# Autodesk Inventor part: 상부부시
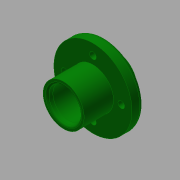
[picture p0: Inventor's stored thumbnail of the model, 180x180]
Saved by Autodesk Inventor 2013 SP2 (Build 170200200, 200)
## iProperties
Created: 2015-12
Part Number: 상부부시
Material: 강철, 연강
Document SubType Name: Modeling
Designer: mduedu
Density: 7.86 g/cm^3
Author: mduedu
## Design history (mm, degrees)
sketch "스케치1"
  geometry: C1 r 10.5 at (0, 0); C2 r 8 at (0, 0); 1 further point
  constraints: 2 centre point, 2 coincident
  dimensions: "d1" = 21 diameter of C1; "d3" = 16 diameter of C2
extrude "돌출1" new body sketch "스케치1" distance "d4" = 12; taper "d6" = 0 deg; dims "d5" = 15, "d7" = 0
sketch "스케치2"
  geometry: C1 r 20 at (0, 0); C2 r 10.5 at (0, 0) reference; 1 further point
  constraints: 1 centre point, 1 coincident
  dimensions: "d8" = 40 diameter of C1
extrude "돌출2" join sketch "스케치2" distance "d10" = 6; taper "d11" = 0 deg
chamfer "모따기1" distance "d12" = 2.5; stored, may be unused: second distance "d13" = 2, angle "d14" = 10 deg
chamfer "모따기2" distance "d15" = 2.5; stored, may be unused: second distance "d16" = 2, angle "d17" = 10 deg
fillet "모깎기1" dims "d18" = 1
fillet "모깎기2" dims "d19" = 2
sketch "스케치3" dims "d20" = 29
  geometry: 6 further points
  constraints: 2 vertical alignment, 1 coincident, 7 other
  dimensions: "d24" = 360 deg dimension on point (0, 0) point (0, 14.5) (derived)
sketch "스케치4"
  geometry: 4 further points
hole "구멍1" sketch "스케치4" at (-14.5, 0), (0, -14.5), (14.5, 0), (0, 14.5) diameter "d26" = 3.4; stored, may be unused: countersink angle "d30" = 90 deg, drill point angle "d32" = 0 deg; dims "d27" = 6, "d28" = 6.5, "d29" = 3.4, "d31" = 8
fillet "모깎기3" dims "d33" = 1
node "솔리드1"
